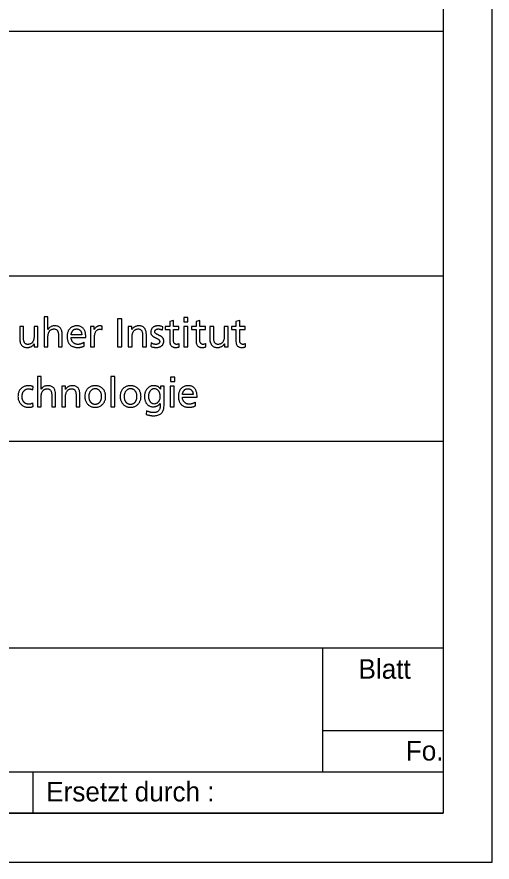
# Model space of a CAD drawing. Extents: x 0 to 210, y 0 to 148.
# Drawn here: x 198.08 to 210.25, y 0 to 21.62 of the extents above; entities that cross this region are included whole.
import ezdxf

# ---------------------------------------------------------------- set-up
doc = ezdxf.new("R2010")
doc.units = 0
doc.layers.add('90_Plankopf', color=7, linetype='Continuous')

msp = doc.modelspace()

# ---------------------------------------------------------------- linework, layer by layer
at = {"layer": '90_Plankopf'}
for p, q in [((209, 21.248), (164.53, 21.248)), ((209, 21.248), (209, 1.25)), ((164.53, 14.998), (209, 14.998)), ((164.53, 14.998), (209, 14.998)), ((209, 14.998), (209, 1.25)), ((200.264, 13.621), (200.264, 13.708)), ((201.808, 13.61), (201.816, 13.694)), ((199.743, 13.49), (199.471, 13.49)), ((199.471, 13.418), (199.846, 13.418)), ((199.806, 13.198), (199.806, 13.295)), ((201.518, 13.28), (201.513, 13.193)), ((202.24, 13.179), (202.24, 13.261)), ((202.916, 13.179), (202.916, 13.261)), ((203.936, 13.179), (203.936, 13.261)), ((198.488, 12.084), (198.496, 12.165)), ((202.593, 11.96), (202.321, 11.96)), ((198.5, 11.656), (198.493, 11.743)), ((202.321, 11.888), (202.696, 11.888)), ((202.656, 11.668), (202.656, 11.765)), ((201.399, 11.543), (201.389, 11.454)), ((188, 10.768), (209, 10.768)), ((188, 5.48), (209, 5.48)), ((205.912, 2.308), (205.912, 5.48)), ((205.912, 3.365), (209, 3.365)), ((188, 2.308), (209, 2.308)), ((198.5, 1.25), (198.5, 2.308)), ((209, 1.25), (164.53, 1.25)), ((167.45, 1.25), (209, 1.25)), ((167.45, 1.25), (209, 1.25))]:
    msp.add_line(p, q, dxfattribs=at)
for points in [[(0, 0), (210.25, 0), (210.25, 148.5), (0, 148.5)], [(6.25, 147.25), (209, 147.25), (209, 1.25), (6.25, 1.25)]]:
    msp.add_lwpolyline(points, close=True, dxfattribs=at)
for points in [[(198.877, 13.627), (198.875, 13.627), (198.875, 13.95), (198.778, 13.95), (198.778, 13.176), (198.875, 13.176), (198.875, 13.42)], [(200.662, 13.176), (200.765, 13.176), (200.765, 13.897), (200.662, 13.897), (200.662, 13.176)], [(202.093, 13.336), (202.093, 13.624), (202.232, 13.624), (202.232, 13.703), (202.093, 13.703), (202.093, 13.855), (201.996, 13.824), (201.996, 13.703), (201.877, 13.703), (201.877, 13.624), (201.996, 13.624), (201.996, 13.317)], [(202.463, 13.82), (202.463, 13.93), (202.354, 13.93), (202.354, 13.82), (202.463, 13.82)], [(202.769, 13.336), (202.769, 13.624), (202.908, 13.624), (202.908, 13.703), (202.769, 13.703), (202.769, 13.855), (202.672, 13.824), (202.672, 13.703), (202.553, 13.703), (202.553, 13.624), (202.672, 13.624), (202.672, 13.317)], [(203.788, 13.336), (203.788, 13.624), (203.928, 13.624), (203.928, 13.703), (203.788, 13.703), (203.788, 13.855), (203.691, 13.824), (203.691, 13.703), (203.573, 13.703), (203.573, 13.624), (203.691, 13.624), (203.691, 13.317)], [(198.251, 13.43), (198.251, 13.703), (198.154, 13.703), (198.154, 13.39)], [(198.523, 13.26), (198.525, 13.26), (198.525, 13.176), (198.619, 13.176), (198.619, 13.703), (198.522, 13.703), (198.522, 13.459)], [(200.063, 13.621), (200.061, 13.621), (200.061, 13.703), (199.97, 13.703), (199.97, 13.176), (200.067, 13.176), (200.067, 13.416)], [(201.029, 13.619), (201.027, 13.619), (201.027, 13.703), (200.933, 13.703), (200.933, 13.176), (201.03, 13.176), (201.03, 13.42)], [(202.36, 13.703), (202.36, 13.176), (202.457, 13.176), (202.457, 13.703), (202.36, 13.703)], [(203.121, 13.43), (203.121, 13.703), (203.024, 13.703), (203.024, 13.39)], [(203.393, 13.26), (203.395, 13.26), (203.395, 13.176), (203.489, 13.176), (203.489, 13.703), (203.392, 13.703), (203.392, 13.459)], [(199.147, 13.449), (199.147, 13.176), (199.244, 13.176), (199.244, 13.489)], [(201.301, 13.449), (201.301, 13.176), (201.398, 13.176), (201.398, 13.489)], [(198.705, 12.097), (198.703, 12.097), (198.703, 12.42), (198.606, 12.42), (198.606, 11.647), (198.703, 11.647), (198.703, 11.89)], [(200.491, 11.647), (200.588, 11.647), (200.588, 12.42), (200.491, 12.42), (200.491, 11.647)], [(202.123, 12.29), (202.123, 12.4), (202.014, 12.4), (202.014, 12.29), (202.123, 12.29)], [(199.326, 12.089), (199.324, 12.089), (199.324, 12.173), (199.23, 12.173), (199.23, 11.647), (199.327, 11.647), (199.327, 11.89)], [(201.849, 11.669), (201.849, 12.173), (201.759, 12.173), (201.759, 12.094), (201.757, 12.094)], [(202.008, 12.173), (202.008, 11.647), (202.105, 11.647), (202.105, 12.173), (202.008, 12.173)], [(198.974, 11.919), (198.974, 11.647), (199.071, 11.647), (199.071, 11.959)], [(199.598, 11.919), (199.598, 11.647), (199.695, 11.647), (199.695, 11.959)], [(201.75, 11.728), (201.752, 11.728), (201.752, 11.677)]]:
    msp.add_lwpolyline(points, dxfattribs=at)
for points in [[(198.875, 13.42), (198.875, 13.452), (198.878, 13.481), (198.885, 13.508), (198.891, 13.534), (198.901, 13.557), (198.914, 13.576), (198.927, 13.595), (198.944, 13.61), (198.964, 13.621), (198.984, 13.631), (199.008, 13.636), (199.035, 13.637), (199.063, 13.635), (199.085, 13.627), (199.102, 13.613), (199.118, 13.599), (199.13, 13.578), (199.137, 13.551), (199.144, 13.524), (199.147, 13.49), (199.147, 13.449)], [(199.244, 13.489), (199.244, 13.536), (199.237, 13.577), (199.223, 13.61), (199.209, 13.644), (199.187, 13.67), (199.158, 13.688), (199.129, 13.706), (199.092, 13.715), (199.047, 13.715), (199.01, 13.715), (198.977, 13.707), (198.948, 13.692), (198.919, 13.677), (198.895, 13.655), (198.877, 13.627)], [(199.846, 13.418), (199.846, 13.46), (199.842, 13.5), (199.835, 13.536), (199.827, 13.572), (199.814, 13.603), (199.796, 13.63), (199.778, 13.657), (199.754, 13.677), (199.724, 13.692), (199.695, 13.707), (199.658, 13.715), (199.614, 13.715), (199.577, 13.715), (199.543, 13.708), (199.513, 13.695), (199.483, 13.682), (199.457, 13.664), (199.435, 13.64), (199.414, 13.617), (199.397, 13.589), (199.385, 13.556), (199.374, 13.524), (199.368, 13.488), (199.368, 13.449), (199.368, 13.406), (199.373, 13.367), (199.384, 13.332), (199.395, 13.297), (199.411, 13.267), (199.434, 13.242), (199.456, 13.217), (199.484, 13.198), (199.519, 13.184), (199.553, 13.171), (199.593, 13.164), (199.64, 13.164), (199.669, 13.164), (199.693, 13.166), (199.713, 13.17), (199.733, 13.174), (199.751, 13.178), (199.766, 13.183), (199.78, 13.188), (199.794, 13.193), (199.806, 13.198)], [(199.471, 13.49), (199.472, 13.507), (199.476, 13.524), (199.483, 13.542), (199.489, 13.559), (199.497, 13.574), (199.509, 13.589), (199.52, 13.603), (199.534, 13.615), (199.551, 13.623), (199.568, 13.632), (199.588, 13.636), (199.612, 13.637), (199.633, 13.636), (199.652, 13.633), (199.668, 13.625), (199.684, 13.617), (199.698, 13.607), (199.709, 13.594), (199.72, 13.58), (199.729, 13.564), (199.734, 13.547), (199.74, 13.529), (199.743, 13.51), (199.743, 13.49)], [(200.264, 13.708), (200.258, 13.709), (200.251, 13.71), (200.245, 13.712), (200.239, 13.713), (200.232, 13.713), (200.225, 13.714), (200.218, 13.715), (200.21, 13.715), (200.2, 13.715), (200.182, 13.715), (200.163, 13.711), (200.146, 13.703), (200.128, 13.695), (200.112, 13.684), (200.098, 13.67), (200.083, 13.656), (200.072, 13.639), (200.063, 13.621)], [(200.067, 13.416), (200.067, 13.46), (200.073, 13.498), (200.085, 13.53), (200.097, 13.562), (200.113, 13.587), (200.135, 13.604), (200.156, 13.621), (200.182, 13.63), (200.211, 13.63), (200.219, 13.631), (200.228, 13.63), (200.237, 13.629), (200.246, 13.627), (200.255, 13.625), (200.264, 13.621)], [(201.398, 13.489), (201.398, 13.536), (201.391, 13.577), (201.377, 13.61), (201.364, 13.644), (201.342, 13.67), (201.313, 13.688), (201.284, 13.706), (201.247, 13.715), (201.201, 13.715), (201.177, 13.715), (201.153, 13.711), (201.13, 13.704), (201.108, 13.696), (201.088, 13.685), (201.07, 13.67), (201.053, 13.656), (201.039, 13.639), (201.029, 13.619)], [(201.03, 13.42), (201.03, 13.452), (201.033, 13.481), (201.039, 13.508), (201.046, 13.534), (201.055, 13.557), (201.069, 13.576), (201.082, 13.595), (201.098, 13.61), (201.118, 13.621), (201.138, 13.631), (201.162, 13.636), (201.19, 13.637), (201.218, 13.635), (201.24, 13.627), (201.256, 13.613), (201.273, 13.599), (201.284, 13.578), (201.291, 13.551), (201.298, 13.524), (201.301, 13.49), (201.301, 13.449)], [(201.816, 13.694), (201.797, 13.7), (201.778, 13.705), (201.759, 13.709), (201.739, 13.713), (201.718, 13.715), (201.696, 13.715), (201.669, 13.715), (201.645, 13.712), (201.623, 13.705), (201.6, 13.698), (201.581, 13.688), (201.564, 13.675), (201.547, 13.662), (201.534, 13.645), (201.524, 13.625), (201.515, 13.604), (201.51, 13.58), (201.51, 13.553), (201.51, 13.532), (201.514, 13.514), (201.523, 13.498), (201.531, 13.483), (201.541, 13.47), (201.555, 13.459), (201.569, 13.447), (201.583, 13.437), (201.6, 13.429), (201.616, 13.42), (201.632, 13.412), (201.648, 13.404), (201.664, 13.397), (201.679, 13.389), (201.693, 13.38), (201.706, 13.373), (201.717, 13.363), (201.725, 13.353), (201.733, 13.343), (201.738, 13.331), (201.738, 13.318), (201.738, 13.304), (201.735, 13.292), (201.729, 13.282), (201.723, 13.272), (201.715, 13.265), (201.705, 13.259), (201.695, 13.253), (201.685, 13.249), (201.673, 13.246), (201.662, 13.244), (201.65, 13.242), (201.639, 13.242), (201.629, 13.242), (201.617, 13.244), (201.604, 13.247), (201.59, 13.249), (201.575, 13.253), (201.56, 13.259), (201.545, 13.265), (201.531, 13.271), (201.518, 13.28)], [(201.513, 13.193), (201.535, 13.181), (201.559, 13.174), (201.583, 13.17), (201.608, 13.166), (201.632, 13.164), (201.657, 13.164), (201.681, 13.164), (201.704, 13.167), (201.726, 13.174), (201.747, 13.18), (201.767, 13.191), (201.784, 13.204), (201.802, 13.217), (201.815, 13.234), (201.826, 13.255), (201.836, 13.276), (201.841, 13.3), (201.841, 13.328), (201.841, 13.352), (201.837, 13.372), (201.828, 13.389), (201.82, 13.406), (201.809, 13.42), (201.796, 13.431), (201.782, 13.443), (201.767, 13.453), (201.751, 13.461), (201.735, 13.469), (201.719, 13.477), (201.703, 13.484), (201.687, 13.491), (201.672, 13.499), (201.658, 13.507), (201.645, 13.515), (201.634, 13.524), (201.626, 13.534), (201.617, 13.545), (201.613, 13.557), (201.613, 13.573), (201.613, 13.587), (201.618, 13.599), (201.626, 13.609), (201.635, 13.618), (201.646, 13.625), (201.66, 13.63), (201.674, 13.634), (201.689, 13.637), (201.706, 13.637), (201.712, 13.637), (201.719, 13.636), (201.728, 13.634), (201.738, 13.633), (201.747, 13.631), (201.757, 13.628), (201.768, 13.626), (201.777, 13.623), (201.786, 13.62), (201.795, 13.616), (201.802, 13.613), (201.808, 13.61)], [(198.522, 13.459), (198.522, 13.427), (198.519, 13.398), (198.513, 13.371), (198.507, 13.345), (198.497, 13.322), (198.484, 13.303), (198.471, 13.284), (198.454, 13.269), (198.434, 13.258), (198.414, 13.248), (198.39, 13.243), (198.362, 13.242), (198.334, 13.244), (198.312, 13.252), (198.296, 13.266), (198.28, 13.28), (198.268, 13.301), (198.261, 13.328), (198.254, 13.355), (198.251, 13.389), (198.251, 13.43)], [(199.806, 13.295), (199.8, 13.29), (199.791, 13.285), (199.78, 13.279), (199.768, 13.273), (199.755, 13.267), (199.74, 13.261), (199.725, 13.256), (199.71, 13.251), (199.693, 13.248), (199.677, 13.244), (199.66, 13.243), (199.644, 13.242), (199.621, 13.243), (199.599, 13.247), (199.578, 13.255), (199.558, 13.264), (199.539, 13.276), (199.523, 13.291), (199.507, 13.307), (199.494, 13.325), (199.485, 13.347), (199.476, 13.368), (199.471, 13.392), (199.471, 13.418)], [(203.392, 13.459), (203.392, 13.427), (203.389, 13.398), (203.383, 13.371), (203.376, 13.345), (203.367, 13.322), (203.354, 13.303), (203.341, 13.284), (203.324, 13.269), (203.304, 13.258), (203.284, 13.248), (203.26, 13.243), (203.232, 13.242), (203.204, 13.244), (203.182, 13.252), (203.166, 13.266), (203.149, 13.28), (203.138, 13.301), (203.131, 13.328), (203.124, 13.355), (203.121, 13.389), (203.121, 13.43)], [(198.154, 13.39), (198.154, 13.343), (198.161, 13.302), (198.175, 13.269), (198.189, 13.235), (198.21, 13.209), (198.24, 13.191), (198.269, 13.173), (198.306, 13.164), (198.351, 13.164), (198.376, 13.164), (198.399, 13.168), (198.422, 13.176), (198.444, 13.183), (198.465, 13.194), (198.482, 13.209), (198.5, 13.223), (198.514, 13.24), (198.523, 13.26)], [(201.996, 13.317), (201.996, 13.282), (202.003, 13.253), (202.016, 13.23), (202.029, 13.208), (202.047, 13.191), (202.071, 13.18), (202.096, 13.169), (202.124, 13.164), (202.158, 13.164), (202.174, 13.164), (202.188, 13.166), (202.203, 13.169), (202.217, 13.172), (202.229, 13.175), (202.24, 13.179)], [(202.24, 13.261), (202.233, 13.256), (202.224, 13.252), (202.213, 13.248), (202.202, 13.245), (202.189, 13.243), (202.174, 13.242), (202.159, 13.242), (202.146, 13.246), (202.133, 13.253), (202.121, 13.261), (202.111, 13.271), (202.104, 13.285), (202.097, 13.299), (202.093, 13.316), (202.093, 13.336)], [(202.672, 13.317), (202.672, 13.282), (202.679, 13.253), (202.692, 13.23), (202.705, 13.208), (202.723, 13.191), (202.747, 13.18), (202.772, 13.169), (202.8, 13.164), (202.834, 13.164), (202.85, 13.164), (202.864, 13.166), (202.879, 13.169), (202.893, 13.172), (202.905, 13.175), (202.916, 13.179)], [(202.916, 13.261), (202.909, 13.256), (202.9, 13.252), (202.889, 13.248), (202.878, 13.245), (202.865, 13.243), (202.85, 13.242), (202.835, 13.242), (202.822, 13.246), (202.809, 13.253), (202.797, 13.261), (202.787, 13.271), (202.78, 13.285), (202.773, 13.299), (202.769, 13.316), (202.769, 13.336)], [(203.024, 13.39), (203.024, 13.343), (203.031, 13.302), (203.045, 13.269), (203.059, 13.235), (203.08, 13.209), (203.109, 13.191), (203.138, 13.173), (203.176, 13.164), (203.221, 13.164), (203.245, 13.164), (203.269, 13.168), (203.292, 13.176), (203.314, 13.183), (203.334, 13.194), (203.352, 13.209), (203.37, 13.223), (203.383, 13.24), (203.393, 13.26)], [(203.691, 13.317), (203.692, 13.282), (203.698, 13.253), (203.711, 13.23), (203.724, 13.208), (203.743, 13.191), (203.767, 13.18), (203.791, 13.169), (203.82, 13.164), (203.853, 13.164), (203.869, 13.164), (203.884, 13.166), (203.898, 13.169), (203.912, 13.172), (203.925, 13.175), (203.936, 13.179)], [(203.936, 13.261), (203.929, 13.256), (203.92, 13.252), (203.909, 13.248), (203.898, 13.245), (203.885, 13.243), (203.87, 13.242), (203.855, 13.242), (203.841, 13.246), (203.829, 13.253), (203.817, 13.261), (203.807, 13.271), (203.8, 13.285), (203.792, 13.299), (203.789, 13.316), (203.788, 13.336)], [(198.496, 12.165), (198.487, 12.168), (198.475, 12.172), (198.462, 12.175), (198.449, 12.178), (198.435, 12.181), (198.42, 12.182), (198.406, 12.184), (198.392, 12.185), (198.378, 12.185), (198.338, 12.185), (198.301, 12.178), (198.269, 12.165), (198.236, 12.151), (198.208, 12.132), (198.184, 12.107), (198.16, 12.083), (198.142, 12.054), (198.129, 12.02), (198.117, 11.987), (198.11, 11.95), (198.11, 11.91), (198.11, 11.872), (198.117, 11.836), (198.13, 11.803), (198.143, 11.77), (198.161, 11.741), (198.185, 11.716), (198.209, 11.69), (198.237, 11.67), (198.269, 11.656), (198.302, 11.642), (198.339, 11.635), (198.378, 11.634), (198.39, 11.634), (198.403, 11.635), (198.417, 11.636), (198.43, 11.637), (198.444, 11.639), (198.459, 11.642), (198.473, 11.645), (198.487, 11.65), (198.5, 11.656)], [(198.493, 11.743), (198.483, 11.736), (198.472, 11.73), (198.46, 11.726), (198.448, 11.722), (198.436, 11.718), (198.424, 11.716), (198.412, 11.714), (198.4, 11.713), (198.389, 11.713), (198.364, 11.713), (198.342, 11.717), (198.323, 11.724), (198.303, 11.732), (198.287, 11.742), (198.273, 11.755), (198.259, 11.768), (198.248, 11.783), (198.239, 11.8), (198.23, 11.817), (198.224, 11.834), (198.22, 11.853), (198.215, 11.872), (198.213, 11.891), (198.213, 11.91), (198.213, 11.935), (198.217, 11.959), (198.225, 11.983), (198.232, 12.006), (198.243, 12.027), (198.257, 12.046), (198.272, 12.064), (198.289, 12.079), (198.31, 12.09), (198.331, 12.101), (198.355, 12.107), (198.383, 12.107), (198.398, 12.107), (198.415, 12.105), (198.433, 12.101), (198.451, 12.097), (198.469, 12.092), (198.488, 12.084)], [(198.703, 11.89), (198.703, 11.922), (198.706, 11.951), (198.712, 11.978), (198.718, 12.004), (198.728, 12.027), (198.741, 12.046), (198.754, 12.066), (198.771, 12.08), (198.791, 12.091), (198.811, 12.101), (198.835, 12.107), (198.862, 12.107), (198.89, 12.105), (198.913, 12.097), (198.929, 12.083), (198.945, 12.069), (198.957, 12.048), (198.964, 12.021), (198.971, 11.994), (198.974, 11.96), (198.974, 11.919)], [(199.071, 11.959), (199.071, 12.006), (199.064, 12.047), (199.05, 12.081), (199.036, 12.114), (199.014, 12.14), (198.985, 12.158), (198.956, 12.176), (198.919, 12.185), (198.874, 12.185), (198.837, 12.185), (198.804, 12.177), (198.775, 12.162), (198.746, 12.147), (198.722, 12.125), (198.705, 12.097)], [(199.695, 11.959), (199.695, 12.006), (199.688, 12.047), (199.674, 12.081), (199.66, 12.114), (199.639, 12.14), (199.61, 12.158), (199.581, 12.176), (199.543, 12.185), (199.498, 12.185), (199.474, 12.185), (199.45, 12.181), (199.427, 12.174), (199.405, 12.166), (199.385, 12.155), (199.367, 12.141), (199.349, 12.126), (199.336, 12.109), (199.326, 12.089)], [(199.327, 11.89), (199.327, 11.922), (199.33, 11.951), (199.336, 11.978), (199.343, 12.004), (199.352, 12.027), (199.365, 12.046), (199.378, 12.066), (199.395, 12.08), (199.415, 12.091), (199.435, 12.101), (199.459, 12.107), (199.487, 12.107), (199.515, 12.105), (199.537, 12.097), (199.553, 12.083), (199.57, 12.069), (199.581, 12.048), (199.588, 12.021), (199.595, 11.994), (199.598, 11.96), (199.598, 11.919)], [(200.349, 11.973), (200.345, 11.989), (200.341, 12.005), (200.335, 12.02), (200.323, 12.054), (200.305, 12.083), (200.281, 12.107), (200.257, 12.132), (200.229, 12.151), (200.197, 12.165), (200.164, 12.178), (200.127, 12.185), (200.087, 12.185), (200.047, 12.185), (200.01, 12.178), (199.977, 12.165), (199.945, 12.151), (199.916, 12.132), (199.893, 12.107), (199.869, 12.083), (199.851, 12.054), (199.838, 12.02), (199.826, 11.987), (199.819, 11.95), (199.819, 11.91)], [(199.922, 11.91), (199.922, 11.935), (199.926, 11.959), (199.933, 11.983), (199.941, 12.006), (199.952, 12.027), (199.966, 12.046), (199.98, 12.064), (199.997, 12.079), (200.018, 12.09), (200.038, 12.101), (200.061, 12.107), (200.087, 12.107), (200.113, 12.107), (200.136, 12.101), (200.156, 12.09), (200.177, 12.079), (200.194, 12.064), (200.208, 12.046), (200.222, 12.027), (200.233, 12.006), (200.24, 11.983), (200.248, 11.959), (200.251, 11.935), (200.251, 11.91), (200.251, 11.891), (200.249, 11.872), (200.245, 11.853), (200.241, 11.834), (200.235, 11.817), (200.226, 11.8), (200.218, 11.783), (200.207, 11.768), (200.194, 11.755), (200.181, 11.742), (200.166, 11.732), (200.148, 11.724), (200.13, 11.717), (200.11, 11.713), (200.087, 11.713), (200.064, 11.713), (200.044, 11.717), (200.026, 11.724), (200.008, 11.732), (199.993, 11.742), (199.98, 11.755), (199.967, 11.768), (199.956, 11.783), (199.947, 11.8), (199.939, 11.817), (199.933, 11.834), (199.928, 11.853), (199.924, 11.872), (199.922, 11.891), (199.922, 11.91)], [(201.254, 11.973), (201.251, 11.989), (201.246, 12.005), (201.24, 12.02), (201.228, 12.054), (201.21, 12.083), (201.186, 12.107), (201.162, 12.132), (201.134, 12.151), (201.102, 12.165), (201.069, 12.178), (201.032, 12.185), (200.992, 12.185), (200.952, 12.185), (200.915, 12.178), (200.883, 12.165), (200.85, 12.151), (200.822, 12.132), (200.798, 12.107), (200.774, 12.083), (200.756, 12.054), (200.743, 12.02), (200.731, 11.987), (200.724, 11.95), (200.724, 11.91)], [(200.827, 11.91), (200.827, 11.935), (200.831, 11.959), (200.838, 11.983), (200.846, 12.006), (200.857, 12.027), (200.871, 12.046), (200.885, 12.064), (200.902, 12.079), (200.923, 12.09), (200.943, 12.101), (200.966, 12.107), (200.992, 12.107), (201.018, 12.107), (201.041, 12.101), (201.062, 12.09), (201.082, 12.079), (201.099, 12.064), (201.113, 12.046), (201.127, 12.027), (201.138, 12.006), (201.145, 11.983), (201.153, 11.959), (201.156, 11.935), (201.156, 11.91), (201.156, 11.891), (201.154, 11.872), (201.15, 11.853), (201.146, 11.834), (201.14, 11.817), (201.131, 11.8), (201.123, 11.783), (201.112, 11.768), (201.099, 11.755), (201.086, 11.742), (201.071, 11.732), (201.053, 11.724), (201.035, 11.717), (201.015, 11.713), (200.992, 11.713), (200.969, 11.713), (200.949, 11.717), (200.931, 11.724), (200.913, 11.732), (200.898, 11.742), (200.885, 11.755), (200.872, 11.768), (200.861, 11.783), (200.852, 11.8), (200.844, 11.817), (200.838, 11.834), (200.833, 11.853), (200.829, 11.872), (200.827, 11.891), (200.827, 11.91)], [(201.757, 12.094), (201.747, 12.113), (201.735, 12.13), (201.72, 12.143), (201.705, 12.157), (201.686, 12.167), (201.663, 12.174), (201.641, 12.181), (201.614, 12.185), (201.584, 12.185), (201.552, 12.185), (201.523, 12.18), (201.498, 12.169), (201.473, 12.158), (201.451, 12.144), (201.432, 12.126), (201.413, 12.107), (201.398, 12.086), (201.385, 12.062), (201.373, 12.039), (201.364, 12.013), (201.358, 11.987), (201.352, 11.96), (201.348, 11.933), (201.348, 11.906), (201.348, 11.871), (201.353, 11.839), (201.362, 11.808), (201.372, 11.777), (201.386, 11.749), (201.405, 11.725), (201.423, 11.701), (201.446, 11.682), (201.475, 11.668), (201.503, 11.654), (201.536, 11.647), (201.573, 11.647), (201.596, 11.647), (201.618, 11.65), (201.64, 11.656), (201.661, 11.662), (201.682, 11.671), (201.701, 11.683), (201.719, 11.695), (201.736, 11.71), (201.75, 11.728)], [(201.598, 11.725), (201.575, 11.725), (201.555, 11.73), (201.537, 11.74), (201.519, 11.75), (201.503, 11.764), (201.491, 11.781), (201.478, 11.798), (201.468, 11.818), (201.462, 11.84), (201.455, 11.862), (201.452, 11.886), (201.452, 11.911), (201.452, 11.929), (201.453, 11.947), (201.457, 11.966), (201.461, 11.984), (201.467, 12.002), (201.475, 12.018), (201.483, 12.035), (201.492, 12.05), (201.504, 12.064), (201.516, 12.077), (201.53, 12.087), (201.545, 12.095), (201.561, 12.103), (201.579, 12.107), (201.598, 12.107), (201.624, 12.107), (201.646, 12.101), (201.666, 12.09), (201.685, 12.08), (201.701, 12.065), (201.714, 12.046), (201.726, 12.027), (201.736, 12.006), (201.742, 11.981), (201.749, 11.957), (201.752, 11.931), (201.752, 11.903), (201.752, 11.879), (201.748, 11.856), (201.741, 11.834), (201.733, 11.813), (201.723, 11.794), (201.709, 11.777), (201.695, 11.761), (201.679, 11.748), (201.66, 11.739), (201.642, 11.73), (201.621, 11.725), (201.598, 11.725)], [(202.696, 11.888), (202.696, 11.931), (202.693, 11.97), (202.685, 12.006), (202.677, 12.042), (202.664, 12.073), (202.646, 12.1), (202.628, 12.127), (202.604, 12.148), (202.574, 12.162), (202.545, 12.177), (202.508, 12.185), (202.464, 12.185), (202.427, 12.185), (202.393, 12.178), (202.363, 12.166), (202.333, 12.152), (202.307, 12.134), (202.285, 12.111), (202.264, 12.087), (202.247, 12.059), (202.235, 12.026), (202.224, 11.994), (202.218, 11.958), (202.218, 11.919), (202.218, 11.876), (202.223, 11.837), (202.234, 11.802), (202.245, 11.767), (202.261, 11.737), (202.284, 11.712), (202.306, 11.687), (202.334, 11.668), (202.369, 11.655), (202.403, 11.641), (202.443, 11.634), (202.49, 11.634), (202.519, 11.634), (202.543, 11.636), (202.563, 11.64), (202.584, 11.644), (202.601, 11.648), (202.616, 11.653), (202.63, 11.659), (202.644, 11.664), (202.656, 11.668)], [(202.321, 11.96), (202.323, 11.977), (202.326, 11.995), (202.333, 12.012), (202.339, 12.029), (202.347, 12.045), (202.359, 12.059), (202.37, 12.073), (202.384, 12.085), (202.401, 12.093), (202.418, 12.102), (202.438, 12.107), (202.462, 12.107), (202.483, 12.107), (202.502, 12.103), (202.518, 12.095), (202.534, 12.088), (202.548, 12.077), (202.559, 12.064), (202.57, 12.05), (202.579, 12.035), (202.584, 12.017), (202.59, 11.999), (202.593, 11.981), (202.593, 11.96)], [(199.819, 11.91), (199.819, 11.872), (199.826, 11.836), (199.839, 11.803), (199.852, 11.77), (199.87, 11.741), (199.894, 11.716), (199.917, 11.69), (199.946, 11.67), (199.978, 11.656), (200.011, 11.642), (200.047, 11.635), (200.087, 11.634), (200.127, 11.635), (200.163, 11.642), (200.196, 11.656), (200.228, 11.67), (200.257, 11.69), (200.28, 11.716), (200.304, 11.741), (200.322, 11.77), (200.335, 11.803), (200.348, 11.836), (200.354, 11.872), (200.354, 11.91), (200.354, 11.932), (200.352, 11.953), (200.349, 11.973)], [(200.724, 11.91), (200.724, 11.872), (200.731, 11.836), (200.744, 11.803), (200.757, 11.77), (200.775, 11.741), (200.799, 11.716), (200.822, 11.69), (200.851, 11.67), (200.883, 11.656), (200.916, 11.642), (200.952, 11.635), (200.992, 11.634), (201.032, 11.635), (201.068, 11.642), (201.101, 11.656), (201.133, 11.67), (201.162, 11.69), (201.185, 11.716), (201.209, 11.741), (201.227, 11.77), (201.24, 11.803), (201.253, 11.836), (201.259, 11.872), (201.26, 11.91), (201.259, 11.932), (201.258, 11.953), (201.254, 11.973)], [(201.752, 11.677), (201.752, 11.639), (201.745, 11.607), (201.732, 11.58), (201.719, 11.553), (201.701, 11.533), (201.677, 11.518), (201.652, 11.504), (201.623, 11.496), (201.589, 11.496), (201.571, 11.496), (201.555, 11.497), (201.54, 11.499), (201.524, 11.5), (201.51, 11.503), (201.495, 11.507), (201.48, 11.511), (201.466, 11.516), (201.45, 11.522), (201.434, 11.528), (201.417, 11.535), (201.399, 11.543)], [(202.656, 11.765), (202.65, 11.76), (202.641, 11.755), (202.63, 11.749), (202.618, 11.743), (202.605, 11.737), (202.59, 11.732), (202.575, 11.726), (202.56, 11.722), (202.543, 11.718), (202.527, 11.715), (202.51, 11.713), (202.494, 11.713), (202.471, 11.713), (202.449, 11.717), (202.428, 11.725), (202.408, 11.734), (202.389, 11.746), (202.373, 11.761), (202.357, 11.777), (202.344, 11.795), (202.335, 11.817), (202.326, 11.838), (202.321, 11.862), (202.321, 11.888)], [(201.389, 11.454), (201.417, 11.444), (201.441, 11.437), (201.463, 11.431), (201.484, 11.426), (201.504, 11.423), (201.523, 11.42), (201.541, 11.418), (201.559, 11.418), (201.578, 11.418), (201.64, 11.418), (201.692, 11.428), (201.732, 11.447), (201.772, 11.467), (201.801, 11.495), (201.82, 11.533), (201.84, 11.57), (201.849, 11.616), (201.849, 11.669)]]:
    msp.add_open_spline(points, degree=3, dxfattribs=at)

# ---------------------------------------------------------------- texts
for s, p in [('Blatt', (206.829, 4.69)), ('Fo.', (208.04, 2.598)), ('Ersetzt durch :', (198.832, 1.552))]:
    msp.add_text(s, height=0.5, dxfattribs=at).set_placement(p)

doc.saveas('drawing.dxf')
